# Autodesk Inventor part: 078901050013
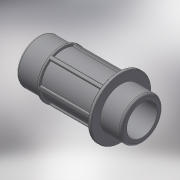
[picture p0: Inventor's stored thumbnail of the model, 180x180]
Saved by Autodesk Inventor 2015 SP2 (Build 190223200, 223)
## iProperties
Created: 2018-02
Part Number: 078901050013
Material: Generic
Description: PLASSON THREADED MALE ADAPTOR 50-1.1/4"
Document SubType Name: Modeling
Designer: KIM
Density: 1 g/cm^3
Appearance: Default
Author: KIM
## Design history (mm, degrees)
derived "078901.ipt"
feature "Solid1::078901.ipt"
tag "TaggingFeature1"
body "Solid1"
other parameters: "d4" = 2.0955, "d14" = 3.3528, "d15" = 1.6764, "d17" = 0, "d20" = 360 deg, "d40" = 24, "d41" = 41.91, "d45" = 46.101, "d46" = 29.337, "d47" = 2.4, "d77" = 104, "d85" = 0.4191, "d91" = 20.8, "d103" = 23.92, "d104" = 69, "d105" = 0.4191, "R_" = 41.91, "E_" = 69, "l_2" = 24, "l_" = 104
